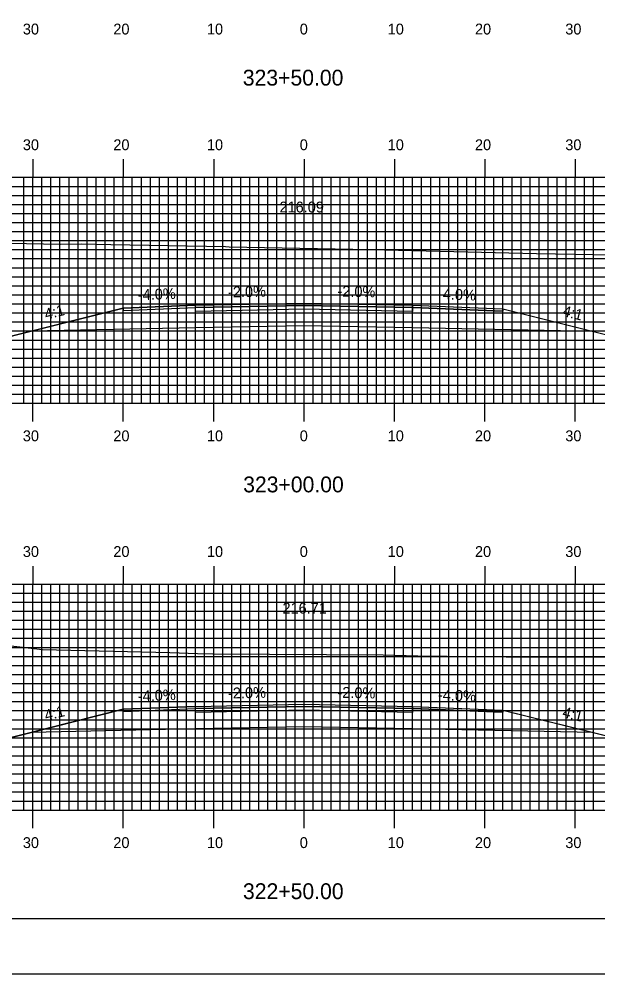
# Model space of a CAD drawing. Extents: x 1820818 to 1821161, y 442591 to 442811.
# Drawn here: x 1820952.2 to 1821016.2, y 442590.5 to 442696.2 of the extents above; entities that cross this region are included whole.
import ezdxf

# ---------------------------------------------------------------- set-up
doc = ezdxf.new("R2010")
doc.units = 0
for name, color, linetype in [('ANNOTATION', 7, 'Continuous'), ('BORDER', 7, 'Continuous'), ('D_Roadway_Centerline', 7, 'Continuous'), ('D_Roadway_Centerline_Text', 7, 'Continuous'), ('D_Roadway_Edge_Shoulder', 7, 'Continuous'), ('D_Roadway_Edge_TW', 7, 'Continuous'), ('D_Roadway_Pavement', 7, 'Continuous'), ('D_Roadway_SlopeLines', 7, 'Continuous'), ('D_Roadway_SubGrade', 7, 'Continuous'), ('H_V ANNOTATION', 7, 'Continuous'), ('MAJOR', 7, 'Continuous'), ('MINOR', 7, 'Continuous'), ('PLOT BOUNDARY', 7, 'Continuous'), ('S_Roadway_Centerline', 7, 'Continuous')]:
    doc.layers.add(name, color=color, linetype=linetype)

msp = doc.modelspace()

# ---------------------------------------------------------------- linework, layer by layer
at = {"layer": 'BORDER'}
msp.add_lwpolyline([(1820834.12, 442596.67), (1821154.12, 442596.67), (1821154.12, 442806.67), (1820834.12, 442806.67)], close=True, dxfattribs=at)
at = {"layer": 'D_Roadway_Centerline'}
for points in [[(1820902.22, 442671.82), (1820903.47, 442671.8), (1820904.72, 442671.69), (1820905.97, 442671.5), (1820907.22, 442671.23), (1820949.54, 442660.65), (1820953.54, 442661.65), (1820963.72, 442664.19), (1820971.72, 442664.51), (1820983.72, 442664.75), (1820995.72, 442664.51), (1821005.72, 442664.11), (1821015.72, 442661.61), (1821019.72, 442660.61), (1821053.37, 442669.03), (1821054.62, 442669.3), (1821055.87, 442669.51), (1821057.12, 442669.64), (1821058.37, 442669.7)], [(1820903.86, 442627.07), (1820905.11, 442627.03), (1820906.36, 442626.91), (1820907.61, 442626.72), (1820908.86, 442626.44), (1820949.54, 442616.27), (1820953.54, 442617.27), (1820963.72, 442619.82), (1820971.72, 442620.14), (1820983.72, 442620.38), (1820995.72, 442620.14), (1821005.72, 442619.74), (1821015.72, 442617.24), (1821019.72, 442616.24), (1821053.46, 442624.67), (1821054.71, 442624.94), (1821055.96, 442625.13), (1821057.21, 442625.24), (1821058.46, 442625.26)]]:
    msp.add_lwpolyline(points, dxfattribs=at)
at = {"layer": 'D_Roadway_Edge_Shoulder'}
for points in [[(1820971.72, 442664.51), (1820963.72, 442664.19), (1820963.72, 442663.94), (1820971.72, 442664.26)], [(1820995.72, 442664.51), (1821005.72, 442664.11), (1821005.72, 442663.86), (1820995.72, 442664.26)], [(1820971.72, 442620.14), (1820963.72, 442619.82), (1820963.72, 442619.57), (1820971.72, 442619.89)], [(1820995.72, 442620.14), (1821005.72, 442619.74), (1821005.72, 442619.49), (1820995.72, 442619.89)]]:
    msp.add_lwpolyline(points, close=True, dxfattribs=at)
at = {"layer": 'D_Roadway_Edge_TW'}
for points in [[(1820971.72, 442664.26), (1820971.72, 442664.51), (1820983.72, 442664.75), (1820995.72, 442664.51), (1820995.72, 442664.26), (1820983.72, 442664.5)], [(1820971.72, 442619.89), (1820971.72, 442620.14), (1820983.72, 442620.38), (1820995.72, 442620.14), (1820995.72, 442619.89), (1820983.72, 442620.13)]]:
    msp.add_lwpolyline(points, close=True, dxfattribs=at)
at = {"layer": 'D_Roadway_Pavement'}
for points in [[(1820971.72, 442663.84), (1820971.72, 442664.26), (1820983.72, 442664.5), (1820995.72, 442664.26), (1820995.72, 442663.84), (1820983.72, 442664.08)], [(1820971.72, 442619.47), (1820971.72, 442619.89), (1820983.72, 442620.13), (1820995.72, 442619.89), (1820995.72, 442619.47), (1820983.72, 442619.71)]]:
    msp.add_lwpolyline(points, close=True, dxfattribs=at)
at = {"layer": 'D_Roadway_SlopeLines'}
for points in [[(1820963.72, 442664.19), (1820949.54, 442660.65)], [(1821005.72, 442664.11), (1821019.72, 442660.61)], [(1820963.72, 442619.82), (1820949.54, 442616.27)], [(1821005.72, 442619.74), (1821019.72, 442616.24)]]:
    msp.add_lwpolyline(points, dxfattribs=at)
at = {"layer": 'D_Roadway_SubGrade'}
for points in [[(1820971.72, 442662.01), (1820953.54, 442661.65), (1820963.72, 442664.19), (1820963.72, 442663.94), (1820971.72, 442664.26), (1820983.72, 442664.5), (1820995.72, 442664.26), (1821005.72, 442663.86), (1821005.72, 442664.11), (1821015.72, 442661.61), (1820995.72, 442662.01), (1820983.72, 442662.25)], [(1820971.72, 442617.64), (1820953.54, 442617.27), (1820963.72, 442619.82), (1820963.72, 442619.57), (1820971.72, 442619.89), (1820983.72, 442620.13), (1820995.72, 442619.89), (1821005.72, 442619.49), (1821005.72, 442619.74), (1821015.72, 442617.24), (1820995.72, 442617.64), (1820983.72, 442617.88)]]:
    msp.add_lwpolyline(points, close=True, dxfattribs=at)
at = {"layer": 'MAJOR'}
for p, q in [((1820953.72, 442680.67), (1820953.72, 442678.67)), ((1820963.72, 442680.67), (1820963.72, 442678.67)), ((1820973.72, 442680.67), (1820973.72, 442678.67)), ((1820983.72, 442680.67), (1820983.72, 442678.67)), ((1820993.72, 442680.67), (1820993.72, 442678.67)), ((1821003.72, 442680.67), (1821003.72, 442678.67)), ((1821013.72, 442680.67), (1821013.72, 442678.67)), ((1820843.72, 442678.67), (1821123.72, 442678.67)), ((1820843.72, 442678.67), (1821123.72, 442678.67)), ((1820953.72, 442653.67), (1820953.72, 442678.67)), ((1820963.72, 442653.67), (1820963.72, 442678.67)), ((1820973.72, 442653.67), (1820973.72, 442678.67)), ((1820983.72, 442653.67), (1820983.72, 442678.67)), ((1820993.72, 442653.67), (1820993.72, 442678.67)), ((1821003.72, 442653.67), (1821003.72, 442678.67)), ((1821013.72, 442653.67), (1821013.72, 442678.67)), ((1820843.72, 442673.67), (1821123.72, 442673.67)), ((1820843.72, 442668.67), (1821123.72, 442668.67)), ((1820843.72, 442663.67), (1821123.72, 442663.67)), ((1820843.72, 442658.67), (1821123.72, 442658.67)), ((1820843.72, 442653.67), (1821123.72, 442653.67)), ((1820843.72, 442653.67), (1821123.72, 442653.67)), ((1820953.72, 442651.66), (1820953.72, 442653.67)), ((1820963.72, 442651.66), (1820963.72, 442653.67)), ((1820973.72, 442651.66), (1820973.72, 442653.67)), ((1820983.72, 442651.66), (1820983.72, 442653.67)), ((1820993.72, 442651.66), (1820993.72, 442653.67)), ((1821003.72, 442651.66), (1821003.72, 442653.67)), ((1821013.72, 442651.66), (1821013.72, 442653.67)), ((1820953.72, 442635.67), (1820953.72, 442633.67)), ((1820963.72, 442635.67), (1820963.72, 442633.67)), ((1820973.72, 442635.67), (1820973.72, 442633.67)), ((1820983.72, 442635.67), (1820983.72, 442633.67)), ((1820993.72, 442635.67), (1820993.72, 442633.67)), ((1821003.72, 442635.67), (1821003.72, 442633.67)), ((1821013.72, 442635.67), (1821013.72, 442633.67)), ((1820843.72, 442633.67), (1821123.72, 442633.67)), ((1820843.72, 442633.67), (1821123.72, 442633.67)), ((1820953.72, 442608.67), (1820953.72, 442633.67)), ((1820963.72, 442608.67), (1820963.72, 442633.67)), ((1820973.72, 442608.67), (1820973.72, 442633.67)), ((1820983.72, 442608.67), (1820983.72, 442633.67)), ((1820993.72, 442608.67), (1820993.72, 442633.67)), ((1821003.72, 442608.67), (1821003.72, 442633.67)), ((1821013.72, 442608.67), (1821013.72, 442633.67)), ((1820843.72, 442628.67), (1821123.72, 442628.67)), ((1820843.72, 442623.67), (1821123.72, 442623.67)), ((1820843.72, 442618.67), (1821123.72, 442618.67)), ((1820843.72, 442613.67), (1821123.72, 442613.67)), ((1820843.72, 442608.67), (1821123.72, 442608.67)), ((1820843.72, 442608.67), (1821123.72, 442608.67)), ((1820953.72, 442606.66), (1820953.72, 442608.67)), ((1820963.72, 442606.66), (1820963.72, 442608.67)), ((1820973.72, 442606.66), (1820973.72, 442608.67)), ((1820983.72, 442606.66), (1820983.72, 442608.67)), ((1820993.72, 442606.66), (1820993.72, 442608.67)), ((1821003.72, 442606.66), (1821003.72, 442608.67)), ((1821013.72, 442606.66), (1821013.72, 442608.67))]:
    msp.add_line(p, q, dxfattribs=at)
at = {"layer": 'MINOR'}
for p, q in [((1820952.72, 442653.67), (1820952.72, 442678.67)), ((1820954.72, 442653.67), (1820954.72, 442678.67)), ((1820955.72, 442653.67), (1820955.72, 442678.67)), ((1820956.72, 442653.67), (1820956.72, 442678.67)), ((1820957.72, 442653.67), (1820957.72, 442678.67)), ((1820958.72, 442653.67), (1820958.72, 442678.67)), ((1820959.72, 442653.67), (1820959.72, 442678.67)), ((1820960.72, 442653.67), (1820960.72, 442678.67)), ((1820961.72, 442653.67), (1820961.72, 442678.67)), ((1820962.72, 442653.67), (1820962.72, 442678.67)), ((1820964.72, 442653.67), (1820964.72, 442678.67)), ((1820965.72, 442653.67), (1820965.72, 442678.67)), ((1820966.72, 442653.67), (1820966.72, 442678.67)), ((1820967.72, 442653.67), (1820967.72, 442678.67)), ((1820968.72, 442653.67), (1820968.72, 442678.67)), ((1820969.72, 442653.67), (1820969.72, 442678.67)), ((1820970.72, 442653.67), (1820970.72, 442678.67)), ((1820971.72, 442653.67), (1820971.72, 442678.67)), ((1820972.72, 442653.67), (1820972.72, 442678.67)), ((1820974.72, 442653.67), (1820974.72, 442678.67)), ((1820975.72, 442653.67), (1820975.72, 442678.67)), ((1820976.72, 442653.67), (1820976.72, 442678.67)), ((1820977.72, 442653.67), (1820977.72, 442678.67)), ((1820978.72, 442653.67), (1820978.72, 442678.67)), ((1820979.72, 442653.67), (1820979.72, 442678.67)), ((1820980.72, 442653.67), (1820980.72, 442678.67)), ((1820981.72, 442653.67), (1820981.72, 442678.67)), ((1820982.72, 442653.67), (1820982.72, 442678.67)), ((1820984.72, 442653.67), (1820984.72, 442678.67)), ((1820985.72, 442653.67), (1820985.72, 442678.67)), ((1820986.72, 442653.67), (1820986.72, 442678.67)), ((1820987.72, 442653.67), (1820987.72, 442678.67)), ((1820988.72, 442653.67), (1820988.72, 442678.67)), ((1820989.72, 442653.67), (1820989.72, 442678.67)), ((1820990.72, 442653.67), (1820990.72, 442678.67)), ((1820991.72, 442653.67), (1820991.72, 442678.67)), ((1820992.72, 442653.67), (1820992.72, 442678.67)), ((1820994.72, 442653.67), (1820994.72, 442678.67)), ((1820995.72, 442653.67), (1820995.72, 442678.67)), ((1820996.72, 442653.67), (1820996.72, 442678.67)), ((1820997.72, 442653.67), (1820997.72, 442678.67)), ((1820998.72, 442653.67), (1820998.72, 442678.67)), ((1820999.72, 442653.67), (1820999.72, 442678.67)), ((1821000.72, 442653.67), (1821000.72, 442678.67)), ((1821001.72, 442653.67), (1821001.72, 442678.67)), ((1821002.72, 442653.67), (1821002.72, 442678.67)), ((1821004.72, 442653.67), (1821004.72, 442678.67)), ((1821005.72, 442653.67), (1821005.72, 442678.67)), ((1821006.72, 442653.67), (1821006.72, 442678.67)), ((1821007.72, 442653.67), (1821007.72, 442678.67)), ((1821008.72, 442653.67), (1821008.72, 442678.67)), ((1821009.72, 442653.67), (1821009.72, 442678.67)), ((1821010.72, 442653.67), (1821010.72, 442678.67)), ((1821011.72, 442653.67), (1821011.72, 442678.67)), ((1821012.72, 442653.67), (1821012.72, 442678.67)), ((1821014.72, 442653.67), (1821014.72, 442678.67)), ((1821015.72, 442653.67), (1821015.72, 442678.67)), ((1820843.72, 442677.67), (1821123.72, 442677.67)), ((1820843.72, 442676.67), (1821123.72, 442676.67)), ((1820843.72, 442675.67), (1821123.72, 442675.67)), ((1820843.72, 442674.67), (1821123.72, 442674.67)), ((1820843.72, 442672.67), (1821123.72, 442672.67)), ((1820843.72, 442671.67), (1821123.72, 442671.67)), ((1820843.72, 442670.67), (1821123.72, 442670.67)), ((1820843.72, 442669.67), (1821123.72, 442669.67)), ((1820843.72, 442667.67), (1821123.72, 442667.67)), ((1820843.72, 442666.67), (1821123.72, 442666.67)), ((1820843.72, 442665.67), (1821123.72, 442665.67)), ((1820843.72, 442664.67), (1821123.72, 442664.67)), ((1820843.72, 442662.67), (1821123.72, 442662.67)), ((1820843.72, 442661.67), (1821123.72, 442661.67)), ((1820843.72, 442660.67), (1821123.72, 442660.67)), ((1820843.72, 442659.67), (1821123.72, 442659.67)), ((1820843.72, 442657.67), (1821123.72, 442657.67)), ((1820843.72, 442656.67), (1821123.72, 442656.67)), ((1820843.72, 442655.67), (1821123.72, 442655.67)), ((1820843.72, 442654.67), (1821123.72, 442654.67)), ((1820952.72, 442608.67), (1820952.72, 442633.67)), ((1820954.72, 442608.67), (1820954.72, 442633.67)), ((1820955.72, 442608.67), (1820955.72, 442633.67)), ((1820956.72, 442608.67), (1820956.72, 442633.67)), ((1820957.72, 442608.67), (1820957.72, 442633.67)), ((1820958.72, 442608.67), (1820958.72, 442633.67)), ((1820959.72, 442608.67), (1820959.72, 442633.67)), ((1820960.72, 442608.67), (1820960.72, 442633.67)), ((1820961.72, 442608.67), (1820961.72, 442633.67)), ((1820962.72, 442608.67), (1820962.72, 442633.67)), ((1820964.72, 442608.67), (1820964.72, 442633.67)), ((1820965.72, 442608.67), (1820965.72, 442633.67)), ((1820966.72, 442608.67), (1820966.72, 442633.67)), ((1820967.72, 442608.67), (1820967.72, 442633.67)), ((1820968.72, 442608.67), (1820968.72, 442633.67)), ((1820969.72, 442608.67), (1820969.72, 442633.67)), ((1820970.72, 442608.67), (1820970.72, 442633.67)), ((1820971.72, 442608.67), (1820971.72, 442633.67)), ((1820972.72, 442608.67), (1820972.72, 442633.67)), ((1820974.72, 442608.67), (1820974.72, 442633.67)), ((1820975.72, 442608.67), (1820975.72, 442633.67)), ((1820976.72, 442608.67), (1820976.72, 442633.67)), ((1820977.72, 442608.67), (1820977.72, 442633.67)), ((1820978.72, 442608.67), (1820978.72, 442633.67)), ((1820979.72, 442608.67), (1820979.72, 442633.67)), ((1820980.72, 442608.67), (1820980.72, 442633.67)), ((1820981.72, 442608.67), (1820981.72, 442633.67)), ((1820982.72, 442608.67), (1820982.72, 442633.67)), ((1820984.72, 442608.67), (1820984.72, 442633.67)), ((1820985.72, 442608.67), (1820985.72, 442633.67)), ((1820986.72, 442608.67), (1820986.72, 442633.67)), ((1820987.72, 442608.67), (1820987.72, 442633.67)), ((1820988.72, 442608.67), (1820988.72, 442633.67)), ((1820989.72, 442608.67), (1820989.72, 442633.67)), ((1820990.72, 442608.67), (1820990.72, 442633.67)), ((1820991.72, 442608.67), (1820991.72, 442633.67)), ((1820992.72, 442608.67), (1820992.72, 442633.67)), ((1820994.72, 442608.67), (1820994.72, 442633.67)), ((1820995.72, 442608.67), (1820995.72, 442633.67)), ((1820996.72, 442608.67), (1820996.72, 442633.67)), ((1820997.72, 442608.67), (1820997.72, 442633.67)), ((1820998.72, 442608.67), (1820998.72, 442633.67)), ((1820999.72, 442608.67), (1820999.72, 442633.67)), ((1821000.72, 442608.67), (1821000.72, 442633.67)), ((1821001.72, 442608.67), (1821001.72, 442633.67)), ((1821002.72, 442608.67), (1821002.72, 442633.67)), ((1821004.72, 442608.67), (1821004.72, 442633.67)), ((1821005.72, 442608.67), (1821005.72, 442633.67)), ((1821006.72, 442608.67), (1821006.72, 442633.67)), ((1821007.72, 442608.67), (1821007.72, 442633.67)), ((1821008.72, 442608.67), (1821008.72, 442633.67)), ((1821009.72, 442608.67), (1821009.72, 442633.67)), ((1821010.72, 442608.67), (1821010.72, 442633.67)), ((1821011.72, 442608.67), (1821011.72, 442633.67)), ((1821012.72, 442608.67), (1821012.72, 442633.67)), ((1821014.72, 442608.67), (1821014.72, 442633.67)), ((1821015.72, 442608.67), (1821015.72, 442633.67)), ((1820843.72, 442632.67), (1821123.72, 442632.67)), ((1820843.72, 442631.67), (1821123.72, 442631.67)), ((1820843.72, 442630.67), (1821123.72, 442630.67)), ((1820843.72, 442629.67), (1821123.72, 442629.67)), ((1820843.72, 442627.67), (1821123.72, 442627.67)), ((1820843.72, 442626.67), (1821123.72, 442626.67)), ((1820843.72, 442625.67), (1821123.72, 442625.67)), ((1820843.72, 442624.67), (1821123.72, 442624.67)), ((1820843.72, 442622.67), (1821123.72, 442622.67)), ((1820843.72, 442621.67), (1821123.72, 442621.67)), ((1820843.72, 442620.67), (1821123.72, 442620.67)), ((1820843.72, 442619.67), (1821123.72, 442619.67)), ((1820843.72, 442617.67), (1821123.72, 442617.67)), ((1820843.72, 442616.67), (1821123.72, 442616.67)), ((1820843.72, 442615.67), (1821123.72, 442615.67)), ((1820843.72, 442614.67), (1821123.72, 442614.67)), ((1820843.72, 442612.67), (1821123.72, 442612.67)), ((1820843.72, 442611.67), (1821123.72, 442611.67)), ((1820843.72, 442610.67), (1821123.72, 442610.67)), ((1820843.72, 442609.67), (1821123.72, 442609.67))]:
    msp.add_line(p, q, dxfattribs=at)
at = {"layer": 'PLOT BOUNDARY'}
msp.add_lwpolyline([(1820817.93, 442590.55), (1821157.93, 442590.55), (1821157.93, 442810.55), (1820817.93, 442810.55)], close=True, dxfattribs=at)
at = {"layer": 'S_Roadway_Centerline'}
for points in [[(1820843.72, 442672.3), (1820844.11, 442672.29), (1820854.74, 442671.9), (1820864.31, 442671.78), (1820874.39, 442671.67), (1820887.74, 442671.75), (1820897.44, 442671.77), (1820906.98, 442671.88), (1820930.49, 442671.78), (1820956.79, 442671.27), (1820959.09, 442671.32), (1820962.35, 442671.22), (1820975.01, 442671), (1820975.43, 442670.99), (1820991.07, 442670.68), (1820998.78, 442670.49), (1821009.44, 442670.25), (1821021.98, 442670.01)], [(1820843.72, 442627.44), (1820847.28, 442627.37), (1820853.39, 442627.27), (1820866.09, 442627.29), (1820870.53, 442627.29), (1820879.54, 442627.29), (1820888, 442627.19), (1820901.45, 442627.07), (1820906.36, 442627.07), (1820913.64, 442627.08), (1820920.92, 442627.11), (1820923.26, 442627.42), (1820936.46, 442628.65), (1820946.85, 442627.34), (1820954.79, 442626.43), (1820968.88, 442626.11), (1820971.93, 442625.99), (1820973.61, 442625.96), (1820992.48, 442625.84), (1820996.3, 442625.75), (1821006.07, 442625.62), (1821014.13, 442625.62), (1821023.16, 442625.59)]]:
    msp.add_lwpolyline(points, dxfattribs=at)

# ---------------------------------------------------------------- texts
at = {"layer": 'ANNOTATION'}
for s, rotation, p in [('-4.0%', 2.2906, (1820965.35, 442665.06)), ('-2.0%', 1.1458, (1820975.32, 442665.38)), ('-2.0%', 358.8542, (1820987.4, 442665.48)), ('-4.0%', 357.7094, (1820998.51, 442665.2)), ('4:1', 14.0362, (1820955.17, 442662.92)), ('4:1', 345.9638, (1821012.22, 442663.35)), ('-4.0%', 2.2906, (1820965.35, 442620.68)), ('-2.0%', 1.1458, (1820975.32, 442621.01)), ('-2.0%', 358.8542, (1820987.4, 442621.1)), ('-4.0%', 357.7094, (1820998.51, 442620.83)), ('4:1', 14.0362, (1820955.17, 442618.54)), ('4:1', 345.9638, (1821012.22, 442618.97))]:
    msp.add_text(s, height=1.2, rotation=rotation, dxfattribs=at).set_placement(p)
at = {"layer": 'D_Roadway_Centerline'}
for s, p in [('C', (1820983.71, 442664.75)), ('L', (1820983.72, 442664.74)), ('C', (1820983.71, 442620.38)), ('L', (1820983.72, 442620.37))]:
    msp.add_text(s, height=0.0146, dxfattribs=at).set_placement(p)
at = {"layer": 'D_Roadway_Centerline_Text'}
for s, p in [('216.09', (1820981, 442674.78)), ('216.71', (1820981.33, 442630.41))]:
    msp.add_text(s, height=1.2, dxfattribs=at).set_placement(p)
at = {"layer": 'H_V ANNOTATION'}
for s, height, p in [('30', 1.2, (1820952.61, 442694.47)), ('20', 1.2, (1820962.62, 442694.47)), ('10', 1.2, (1820972.97, 442694.47)), ('0', 1.2, (1820983.24, 442694.47)), ('10', 1.2, (1820992.97, 442694.47)), ('20', 1.2, (1821002.62, 442694.47)), ('30', 1.2, (1821012.61, 442694.47)), ('323+50.00', 1.75, (1820976.94, 442688.82)), ('30', 1.2, (1820952.61, 442681.67)), ('20', 1.2, (1820962.62, 442681.67)), ('10', 1.2, (1820972.97, 442681.67)), ('0', 1.2, (1820983.24, 442681.67)), ('10', 1.2, (1820992.97, 442681.67)), ('20', 1.2, (1821002.62, 442681.67)), ('30', 1.2, (1821012.61, 442681.67)), ('30', 1.2, (1820952.61, 442649.47)), ('20', 1.2, (1820962.62, 442649.47)), ('10', 1.2, (1820972.97, 442649.47)), ('0', 1.2, (1820983.24, 442649.47)), ('10', 1.2, (1820992.97, 442649.47)), ('20', 1.2, (1821002.62, 442649.47)), ('30', 1.2, (1821012.61, 442649.47)), ('323+00.00', 1.75, (1820976.98, 442643.82)), ('30', 1.2, (1820952.61, 442636.67)), ('20', 1.2, (1820962.62, 442636.67)), ('10', 1.2, (1820972.97, 442636.67)), ('0', 1.2, (1820983.24, 442636.67)), ('10', 1.2, (1820992.97, 442636.67)), ('20', 1.2, (1821002.62, 442636.67)), ('30', 1.2, (1821012.61, 442636.67)), ('30', 1.2, (1820952.61, 442604.47)), ('20', 1.2, (1820962.62, 442604.47)), ('10', 1.2, (1820972.97, 442604.47)), ('0', 1.2, (1820983.24, 442604.47)), ('10', 1.2, (1820992.97, 442604.47)), ('20', 1.2, (1821002.62, 442604.47)), ('30', 1.2, (1821012.61, 442604.47)), ('322+50.00', 1.75, (1820976.96, 442598.82))]:
    msp.add_text(s, height=height, dxfattribs=at).set_placement(p)

doc.saveas('drawing.dxf')
